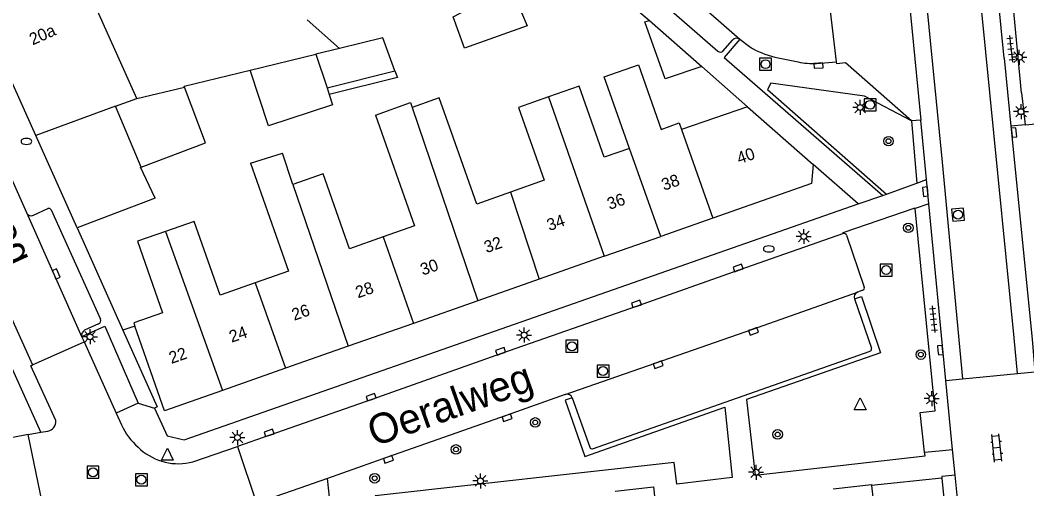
# Model space of a CAD drawing. Extents: x 132994 to 136000, y 393499 to 395512.
# Drawn here: x 133948.7 to 134032.8, y 394394.8 to 394433.9 of the extents above; entities that cross this region are included whole.
import ezdxf

# ---------------------------------------------------------------- set-up
doc = ezdxf.new("R2010")
doc.units = 0
for name, color, linetype in [('gg-afsc-muur', 7, 'Continuous'), ('gg-anno-huisnummerreeks BGT', 7, 'Continuous'), ('gg-anno-openbare ruimte label', 7, 'Continuous'), ('gg-bbg-bijgebouw', 7, 'Continuous'), ('gg-bbg-gedigitaliseerde bebouwing', 7, 'Continuous'), ('gg-bbg-gedigitaliseerde bijgebouw', 7, 'Continuous'), ('gg-bbg-hoofdgebouw', 7, 'Continuous'), ('gg-bbg-luifel en loopbrug', 7, 'Continuous'), ('gg-bbg-tussenscheiding', 7, 'Continuous'), ('gg-knt-verharding', 7, 'Continuous'), ('gg-knt-verharding nz', 7, 'Continuous'), ('gt-grn-groengrens', 7, 'Continuous'), ('gt-grn-weggrens', 7, 'Continuous'), ('gt-symb-boom', 7, 'Continuous'), ('gt-symb-brandkraan', 7, 'Continuous'), ('gt-symb-klinker verharding', 7, 'Continuous'), ('gt-symb-kolk', 7, 'Continuous'), ('gt-symb-lichtmast', 7, 'Continuous'), ('gt-symb-rioolschacht', 7, 'Continuous'), ('gt-symb-tegel verharding', 7, 'Continuous'), ('gt-symb-waterafsluiter', 7, 'Continuous')]:
    doc.layers.add(name, color=color, linetype=linetype)

# ---------------------------------------------------------------- blocks, each defined once
blk = doc.blocks.new('gt0-RS')
at = {"layer": 'gt-symb-rioolschacht'}
blk.add_lwpolyline([(-0.5, -0.5), (0.5, -0.5), (0.5, 0.5), (-0.5, 0.5)], close=True, dxfattribs=at)
blk.add_circle((0, 0), 0.375, dxfattribs=at)
blk = doc.blocks.new('gt0-TEG1')
at = {"layer": 'gt-symb-tegel verharding'}
for p, q in [((-1.125, 0), (1.125, 0)), ((-0.9, -0.25), (-0.9, 0.25)), ((-0.45, -0.25), (-0.45, 0.25)), ((0, -0.25), (0, 0.25)), ((0.45, -0.25), (0.45, 0.25)), ((0.9, -0.25), (0.9, 0.25))]:
    blk.add_line(p, q, dxfattribs=at)
blk = doc.blocks.new('gt0-LMAST')
at = {"layer": 'gt-symb-lichtmast'}
for p, q in [((-0.182, 0.173), (-0.447, 0.438)), ((-0.005, 0.246), (-0.005, 0.621)), ((0.172, 0.173), (0.437, 0.438)), ((-0.255, -0.004), (-0.63, -0.004)), ((-0.182, -0.181), (-0.447, -0.446)), ((-0.005, -0.254), (-0.005, -0.629)), ((0.437, -0.446), (0.172, -0.181)), ((0.245, -0.004), (0.62, -0.004))]:
    blk.add_line(p, q, dxfattribs=at)
blk.add_circle((-0.005, -0.004), 0.25, dxfattribs=at)
blk = doc.blocks.new('gt0-KL1')
at = {"layer": 'gt-symb-klinker verharding'}
for p, q in [((-1.15, 0.3), (1.15, 0.3)), ((-1, -0.3), (-1, 0.3)), ((-0.5, 0.3), (-0.5, 0.45)), ((0, -0.3), (0, 0.3)), ((0.5, 0.3), (0.5, 0.45)), ((1, -0.3), (1, 0.3)), ((-1.15, -0.3), (1.15, -0.3)), ((-0.5, -0.45), (-0.5, -0.3)), ((0.5, -0.45), (0.5, -0.3))]:
    blk.add_line(p, q, dxfattribs=at)
blk = doc.blocks.new('gt0-BOOM')
at = {"layer": 'gt-symb-boom'}
for radius in [0.4, 0.2]:
    blk.add_circle((0, 0), radius, dxfattribs=at)
blk = doc.blocks.new('gt0-KOLK')
at = {"layer": 'gt-symb-kolk'}
blk.add_lwpolyline([(0, 0), (0.375, 0), (0.375, 0.4), (-0.375, 0.4), (-0.375, 0), (0, 0)], dxfattribs=at)
blk = doc.blocks.new('gt0-BR')
at = {"layer": 'gt-symb-brandkraan'}
for centre, radius, start, end in [((-0.244, 0), 0.206, 107.56694, 252.43307), ((0.599, -2.664), 3, 106.89205, 107.56694), ((0, -0.691), 0.938, 73.10799, 106.89205), ((-0.599, -2.664), 3, 72.43309, 73.10799), ((0.244, 0), 0.206, 287.56695, 72.43309), ((0.599, 2.664), 3, 252.43307, 253.10797), ((0, 0.691), 0.938, 253.10797, 286.89206), ((-0.599, 2.664), 3, 286.89206, 287.56695)]:
    blk.add_arc(centre, radius, start, end, dxfattribs=at)
blk = doc.blocks.new('gt0-WAFSL')
at = {"layer": 'gt-symb-waterafsluiter'}
for p, q in [((-0.5, -0.333), (0, 0.667)), ((0, 0.667), (0.5, -0.333)), ((0.5, -0.333), (-0.5, -0.333))]:
    blk.add_line(p, q, dxfattribs=at)

msp = doc.modelspace()

# ---------------------------------------------------------------- linework, layer by layer
at = {"layer": 'gg-afsc-muur'}
for p, q in [((134000, 394434.985), (134001.27, 394433.9)), ((134005.65, 394430.05), (134009.46, 394426.69)), ((133953.43, 394416.58), (133957.263, 394408.027)), ((133958.268, 394408.377), (133957.263, 394408.027))]:
    msp.add_line(p, q, dxfattribs=at)
at = {"layer": 'gg-bbg-bijgebouw'}
for p, q in [((133953.43, 394416.58), (133949.976, 394424.293)), ((133959.97, 394419.06), (133953.43, 394416.58)), ((134016.64, 394394.79), (134019.83, 394395.15)), ((134019.83, 394395.15), (134019.839, 394395.073)), ((134019.839, 394395.073), (134020.12, 394392.64))]:
    msp.add_line(p, q, dxfattribs=at)
msp.add_lwpolyline([(133998.41, 394394.59), (134001.6, 394394.95), (134001.808, 394393.141)], dxfattribs=at)
at = {"layer": 'gg-bbg-gedigitaliseerde bebouwing'}
for p, q in [((133975.368, 394431.554), (133972.67, 394433.937)), ((133992.833, 394427.51), (133990.333, 394426.624)), ((134009.46, 394426.69), (134003.962, 394424.785)), ((133967.92, 394421.971), (133970.593, 394422.806)), ((133971.481, 394420.21), (133970.593, 394422.806)), ((133973.996, 394421.098), (133971.481, 394420.21)), ((133960.82, 394416.279), (133958.49, 394415.46))]:
    msp.add_line(p, q, dxfattribs=at)
for points in [[(133999.602, 394423.218), (133997.494, 394429.191), (134000.348, 394430.199), (134002.253, 394424.802), (134003.768, 394425.336), (134003.962, 394424.785)], [(133962.408, 394428.339), (133962.379, 394428.417), (133967.891, 394429.748)], [(133999.602, 394423.218), (133997.503, 394422.477), (133995.406, 394428.418), (133992.833, 394427.51)], [(133978.365, 394425.999), (133981.303, 394427.036), (133981.446, 394426.631)], [(133984.731, 394424.542), (133983.712, 394427.43), (133981.446, 394426.631)], [(133978.365, 394425.999), (133981.628, 394416.752), (133979.019, 394415.831)], [(133990.333, 394426.624), (133992.477, 394420.551), (133989.661, 394419.557)], [(133989.661, 394419.557), (133986.841, 394418.562), (133984.731, 394424.542)], [(133967.92, 394421.971), (133971.094, 394412.976), (133968.33, 394412.001)], [(133979.019, 394415.831), (133976.205, 394414.838), (133973.996, 394421.098)], [(133968.33, 394412.001), (133965.384, 394410.961), (133963.21, 394417.12), (133960.82, 394416.279)]]:
    msp.add_lwpolyline(points, dxfattribs=at)
at = {"layer": 'gg-bbg-gedigitaliseerde bijgebouw'}
for q in [(133980.003, 394429.7), (133974.513, 394427.71)]:
    msp.add_line((133974.326, 394428.278), q, dxfattribs=at)
for points in [[(133990.589, 394434.569), (133991.045, 394433.438), (133985.803, 394431.581), (133984.881, 394434.184), (133987.056, 394435.324)], [(133980.003, 394429.7), (133979.002, 394432.432), (133975.368, 394431.554)], [(133974.513, 394427.71), (133974.794, 394426.859), (133969.428, 394425.089), (133967.891, 394429.748)], [(133958.787, 394421.655), (133964.177, 394423.669), (133962.408, 394428.339)], [(133959.97, 394419.06), (133958.745, 394421.639), (133958.787, 394421.655)]]:
    msp.add_lwpolyline(points, dxfattribs=at)
at = {"layer": 'gg-bbg-hoofdgebouw'}
for p, q in [((133949.976, 394424.293), (133940.89, 394444.58)), ((134009.46, 394426.69), (134014.97, 394421.88)), ((134006.58, 394417.4), (134002.216, 394415.867)), ((133997.486, 394414.206), (134002.216, 394415.867)), ((133997.486, 394414.206), (133992.071, 394412.305)), ((133992.071, 394412.305), (133986.929, 394410.499)), ((133986.929, 394410.499), (133981.544, 394408.608)), ((133981.544, 394408.608), (133976.102, 394406.698)), ((133976.102, 394406.698), (133970.867, 394404.859)), ((133970.867, 394404.859), (133965.591, 394403.007))]:
    msp.add_line(p, q, dxfattribs=at)
for points in [[(134014.97, 394421.88), (134014.81, 394420.29), (134006.58, 394417.4)], [(133958.49, 394415.46), (133960.56, 394409.49), (133958.17, 394408.66), (133958.268, 394408.377)], [(133965.591, 394403.007), (133960.73, 394401.3), (133958.268, 394408.377)]]:
    msp.add_lwpolyline(points, dxfattribs=at)
at = {"layer": 'gg-bbg-luifel en loopbrug'}
msp.add_line((134001.27, 394433.9), (134005.65, 394430.05), dxfattribs=at)
for points in [[(134005.65, 394430.05), (134002.58, 394429.01), (134000.89, 394433.78), (134001.27, 394433.9)], [(133980.003, 394429.7), (133980.209, 394429.137), (133974.513, 394427.71)]]:
    msp.add_lwpolyline(points, dxfattribs=at)
at = {"layer": 'gg-bbg-tussenscheiding'}
for p, q in [((133958.427, 394427.385), (133951.989, 394441.739)), ((133967.891, 394429.748), (133973.402, 394431.079)), ((133975.368, 394431.554), (133973.402, 394431.079)), ((133973.402, 394431.079), (133974.326, 394428.278)), ((133958.427, 394427.385), (133962.408, 394428.339)), ((133992.833, 394427.51), (133997.486, 394414.206)), ((133956.634, 394426.729), (133949.976, 394424.293)), ((133956.634, 394426.729), (133958.427, 394427.385)), ((133958.787, 394421.655), (133956.634, 394426.729)), ((133981.446, 394426.631), (133986.929, 394410.499)), ((134003.962, 394424.785), (134006.58, 394417.4)), ((134002.216, 394415.867), (133999.602, 394423.218)), ((133971.481, 394420.21), (133976.102, 394406.698)), ((133989.661, 394419.557), (133992.071, 394412.305)), ((133960.82, 394416.279), (133965.591, 394403.007)), ((133979.019, 394415.831), (133981.544, 394408.608)), ((133968.33, 394412.001), (133970.867, 394404.859))]:
    msp.add_line(p, q, dxfattribs=at)
at = {"layer": 'gg-knt-verharding'}
for p, q in [((134032.384, 394427.847), (134029.63, 394456.403)), ((134030.926, 394430.742), (134028.568, 394454.928)), ((134022.443, 394440.97), (134023.96, 394425.579)), ((133998.02, 394439.159), (134006.991, 394431.323)), ((134016.914, 394430.426), (134016.361, 394435.149)), ((134007.412, 394431.328), (134008.22, 394432.259)), ((134008.823, 394432.319), (134009.637, 394431.706)), ((134011.759, 394430.84), (134013.705, 394430.432)), ((134015.236, 394430.314), (134016.914, 394430.426)), ((134030.926, 394430.742), (134031.49, 394425.056)), ((134032.384, 394427.847), (134032.677, 394425.187)), ((134023.96, 394425.579), (134023.189, 394425.516)), ((134024.436, 394420.612), (134023.96, 394425.579)), ((134032.677, 394425.187), (134034.768, 394425.386)), ((133946.913, 394422.931), (133949.193, 394417.856)), ((134018.73, 394418.6), (134014.97, 394421.88)), ((134021.086, 394419.39), (134023.63, 394420.318)), ((134023.63, 394420.318), (134024.436, 394420.612)), ((134024.63, 394418.583), (134024.436, 394420.612)), ((134020.78, 394419.278), (134021.086, 394419.39)), ((134024.63, 394418.583), (134023.489, 394418.198)), ((134026.042, 394403.847), (134024.63, 394418.583)), ((133949.779, 394417.634), (133951, 394418.188)), ((133951.264, 394418.082), (133955.386, 394408.972)), ((134025.161, 394401.297), (134023.489, 394418.198)), ((134017.74, 394415.973), (134019.234, 394411.619)), ((134019.105, 394411.379), (134018.671, 394411.218)), ((133950.397, 394399.512), (133945.687, 394409.964)), ((134018.407, 394410.652), (134019.834, 394406.541)), ((133955.234, 394408.563), (133954.059, 394408.033)), ((133953.832, 394407.503), (133953.845, 394407.467)), ((133953.845, 394407.467), (133954.023, 394407.072)), ((133949.719, 394405.138), (133954.023, 394407.072)), ((133954.023, 394407.072), (133956.702, 394401.113)), ((133996.528, 394398.146), (134019.735, 394406.301)), ((134026.042, 394403.847), (134027.453, 394403.985)), ((134027.453, 394403.985), (134032.025, 394404.431)), ((134032.025, 394404.431), (134033.489, 394404.574)), ((134026.61, 394398.081), (134026.042, 394403.847)), ((133994.825, 394402.4), (133996.279, 394398.272)), ((133958.527, 394401.934), (133956.702, 394401.113)), ((133959.91, 394401.52), (133960.96, 394399.22)), ((133956.702, 394401.113), (133957.146, 394400.125)), ((133949.337, 394399.338), (133946.478, 394398.759)), ((133949.337, 394399.338), (133950.397, 394399.512)), ((133950.852, 394392.062), (133949.337, 394399.338)), ((133950.397, 394399.512), (133950.998, 394399.61)), ((133958.53, 394398.278), (133958.731, 394398.087)), ((133963.109, 394397.049), (133966.829, 394398.333)), ((133966.829, 394398.333), (133968.437, 394393.611)), ((134025.49, 394397.967), (134026.61, 394398.081)), ((134026.821, 394395.941), (134026.61, 394398.081)), ((134024.277, 394397.843), (134025.49, 394397.967)), ((134025.714, 394395.698), (134019.839, 394395.073)), ((134025.702, 394395.815), (134025.714, 394395.698)), ((134025.714, 394395.698), (134030.312, 394349.193)), ((134027.22, 394391.895), (134026.821, 394395.941))]:
    msp.add_line(p, q, dxfattribs=at)
for points in [[(134008.823, 394432.319), (134007.516, 394430.791), (134020.78, 394419.278)], [(134023.189, 394425.516), (134017.667, 394430.346), (134016.932, 394430.279), (134016.914, 394430.426)], [(134031.49, 394425.056), (134033.251, 394407.296), (134033.489, 394404.574)], [(133941.295, 394423.877), (133947.023, 394411.077), (133949.719, 394405.138)], [(133960.96, 394399.22), (133962.38, 394398.88), (134018.73, 394418.6)], [(134017.493, 394416.103), (134017.464, 394416.184), (134023.484, 394418.248), (134023.489, 394418.198)], [(134017.493, 394416.103), (134008.749, 394413.04), (134000.251, 394410.043), (133988.896, 394406.083), (133978.07, 394402.263), (133969.545, 394399.279), (133966.829, 394398.333)], [(134018.407, 394410.652), (134018.986, 394410.848), (134020.595, 394406.145), (134009.399, 394402.254), (134010.124, 394395.936), (134024.311, 394397.538), (134024.277, 394397.843)], [(133953.832, 394407.503), (133955.744, 394408.364), (133958.527, 394401.934)], [(133957.263, 394408.027), (133960.12, 394401.65), (133959.91, 394401.52)], [(133951.659, 394400.489), (133949.566, 394405.067), (133949.719, 394405.138)], [(133994.241, 394402.671), (133989.305, 394400.908), (133979.389, 394397.443), (133974.357, 394395.671)], [(133994.825, 394402.4), (133994.239, 394402.191), (133995.884, 394397.5), (134007.565, 394401.611), (134008.193, 394395.748), (134003.556, 394395.188), (134003.334, 394396.984), (133978.342, 394394.225), (133978.416, 394393.497), (133976.468, 394393.278), (133976.391, 394394.028), (133974.549, 394393.843), (133974.357, 394395.671)], [(134024.277, 394397.843), (134023.901, 394401.173), (134025.161, 394401.297)], [(133974.357, 394395.671), (133971.42, 394394.637), (133968.437, 394393.611)]]:
    msp.add_lwpolyline(points, dxfattribs=at)
for centre, radius, start, end in [((134008.553, 394431.97), 0.441, 52.29044, 139.0743), ((134013.176, 394437.345), 6.657, 237.88764, 257.71107), ((134007.198, 394431.586), 0.335, 231.68957, 309.67131), ((134014.863, 394435.47), 5.17, 257.05172, 274.1337), ((133949.597, 394418.037), 0.442, 204.13272, 294.36994), ((133951.086, 394418.021), 0.188, 18.88477, 117.36282), ((134017.556, 394415.923), 0.191, 15.31842, 109.1645), ((134019.064, 394411.555), 0.181, 282.93344, 20.55051), ((134018.833, 394410.798), 0.451, 111.11428, 198.8741), ((133955.113, 394408.841), 0.303, 293.59745, 25.62858), ((133954.245, 394407.64), 0.435, 115.28253, 198.34638), ((134019.669, 394406.469), 0.18, 291.48035, 23.68736), ((133994.387, 394402.222), 0.472, 22.15077, 108.06276), ((133950.816, 394400.435), 0.845, 282.44138, 3.67296), ((133961.966, 394402.295), 5.286, 204.23554, 229.45461), ((133961.899, 394401.696), 4.802, 228.72709, 284.59646), ((133996.464, 394398.328), 0.193, 196.80478, 289.51421)]:
    msp.add_arc(centre, radius, start, end, dxfattribs=at)
at = {"layer": 'gg-knt-verharding nz'}
msp.add_line((133998.841, 394441.092), (134008.823, 394432.319), dxfattribs=at)
for points in [[(134027.484, 394516.123), (134024.89, 394503.417), (134024.074, 394499.157), (134023.406, 394495.12), (134022.839, 394491.136), (134022.316, 394487.158), (134021.879, 394483.042), (134021.703, 394478.999), (134021.579, 394474.871), (134021.523, 394470.815), (134021.606, 394466.694), (134021.839, 394462.631), (134023.155, 394448.441), (134024.736, 394432.204), (134025.742, 394422.051), (134027.453, 394403.985)], [(134032.025, 394404.431), (134031.767, 394407.387), (134027.702, 394448.389), (134026.575, 394460.449), (134026.291, 394464.499), (134026.051, 394468.495), (134025.968, 394472.486), (134026.046, 394476.526), (134026.228, 394480.511), (134026.559, 394484.566), (134026.947, 394488.154), (134028.588, 394497.502)], [(133949.193, 394417.856), (133951.51, 394412.652), (133953.845, 394407.467)], [(133994.241, 394402.671), (134009.907, 394408.129), (134018.671, 394411.218)]]:
    msp.add_lwpolyline(points, dxfattribs=at)
at = {"layer": 'gt-grn-groengrens'}
msp.add_line((134023.189, 394425.516), (134023.63, 394420.318), dxfattribs=at)
msp.add_lwpolyline([(134023.189, 394425.516), (134019.257, 394427.581), (134011.427, 394428.646), (134011.149, 394428.128), (134021.086, 394419.39)], dxfattribs=at)
at = {"layer": 'gt-grn-weggrens'}
for p, q in [((134032.677, 394425.187), (134031.49, 394425.056)), ((134018.73, 394418.6), (134020.78, 394419.278)), ((133958.527, 394401.934), (133959.91, 394401.52)), ((134026.821, 394395.941), (134025.702, 394395.815))]:
    msp.add_line(p, q, dxfattribs=at)

# ---------------------------------------------------------------- block references
at = {"layer": 'gt-symb-boom'}
for p in [(134021.259, 394423.818), (134022.913, 394416.585), (134023.957, 394406.001), (133991.729, 394400.337), (134011.992, 394399.339), (133985.104, 394398.084), (133978.307, 394395.677)]:
    msp.add_blockref('gt0-BOOM', p, dxfattribs=at)
at = {"layer": 'gt-symb-brandkraan'}
for p in [(133949.198, 394423.796), (134011.254, 394414.821)]:
    msp.add_blockref('gt0-BR', p, dxfattribs=at)
at = {"layer": 'gt-symb-klinker verharding', "rotation": 95.73909849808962}
msp.add_blockref('gt0-KL1', (134030.307, 394398.208), dxfattribs=at)
at = {"layer": 'gt-symb-kolk'}
for p, rotation in [((134015.395, 394430.324), -176.1961248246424), ((134031.552, 394424.525), -84.2609015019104), ((134024.542, 394419.619), 95.22036163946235), ((134008.749, 394413.04), 19.35364427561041), ((133951.51, 394412.652), -65.998180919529), ((134000.251, 394410.043), 19.251581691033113), ((134009.907, 394408.129), -160.58503364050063), ((133988.896, 394406.083), 19.18265317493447), ((134025.391, 394406.349), -84.31791506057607), ((134001.936, 394405.352), -160.72290215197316), ((133978.07, 394402.263), 19.302613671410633), ((133989.305, 394400.908), -160.7815549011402), ((133969.545, 394399.279), 18.825404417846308), ((133979.389, 394397.443), -160.3630040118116)]:
    msp.add_blockref('gt0-KOLK', p, dxfattribs=dict(at, rotation=rotation))
at = {"layer": 'gt-symb-lichtmast'}
for p in [(134032.19, 394430.829), (134018.893, 394426.634), (134032.342, 394426.284), (134014.178, 394415.864), (133990.806, 394407.633), (133954.521, 394407.489), (134024.879, 394402.336), (133966.842, 394399.082), (134010.194, 394396.181), (133987.154, 394395.462)]:
    msp.add_blockref('gt0-LMAST', p, dxfattribs=at)
at = {"layer": 'gt-symb-rioolschacht'}
for p in [(134010.976, 394430.245), (134019.72, 394426.85), (134021.061, 394413.055), (133994.798, 394406.692), (133997.396, 394404.625), (133954.765, 394396.179), (133958.809, 394395.556)]:
    msp.add_blockref('gt0-RS', p, dxfattribs=at)
at = {"layer": 'gt-symb-rioolschacht', "rotation": -174.7225939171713}
msp.add_blockref('gt0-RS', (134027.073, 394417.679), dxfattribs=at)
at = {"layer": 'gt-symb-tegel verharding'}
for p, rotation in [((134031.488, 394431.52), -83.68511557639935), ((134025.017, 394408.953), -84.49452214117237)]:
    msp.add_blockref('gt0-TEG1', p, dxfattribs=dict(at, rotation=rotation))
at = {"layer": 'gt-symb-waterafsluiter'}
for p in [(134018.892, 394401.725), (133960.978, 394397.517)]:
    msp.add_blockref('gt0-WAFSL', p, dxfattribs=at)

# ---------------------------------------------------------------- texts
at = {"layer": 'gg-anno-huisnummerreeks BGT'}
for s, rotation, p in [('20a', 24.1, (133949.717, 394431.804)), ('40', 19.3, (134008.785, 394421.884)), ('38', 19.3, (134002.489, 394419.673)), ('36', 19.3, (133997.942, 394418.076)), ('34', 19.3, (133992.903, 394416.307)), ('32', 19.3, (133987.656, 394414.464)), ('30', 19.3, (133982.327, 394412.593)), ('28', 19.3, (133976.914, 394410.693)), ('26', 19.3, (133971.576, 394408.818)), ('24', 19.3, (133966.354, 394406.985)), ('22', 19.3, (133961.316, 394405.216))]:
    msp.add_text(s, height=1, rotation=rotation, dxfattribs=at).set_placement(p)
at = {"layer": 'gg-anno-openbare ruimte label'}
for rotation, p in [(294.5, (133941.746, 394426.191)), (19.6, (133978.269, 394398.295))]:
    msp.add_text('Oeralweg', height=2.5, rotation=rotation, dxfattribs=at).set_placement(p)

doc.saveas('drawing.dxf')
